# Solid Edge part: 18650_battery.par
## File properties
Last saved by: morva
Revision: 80
Density: 2861.43373586589 kg/m^3
Accuracy: 0.990
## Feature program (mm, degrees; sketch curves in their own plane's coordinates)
body "unnamed Body 1"
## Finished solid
Body 1: solid body, 41 faces, 104 edges, 60 vertices.
  Faces by surface: cylinder 17, torus 17, plane 7
  Edges by curve: circle 68, intersection 24, line 12
Bounding box of the edges (mm; curved faces can reach further): 18.000 x 18.000 x 65.000, from (-9, -9, 0) to (9, 9, 65).
Cylindrical faces by radius (mm): R1 x6, R3.95 x6, R4.25 x1, R6.5 x2, R9 x2
Toroidal faces (ring radius, tube radius in mm): R3.05 r1 x6, R3.2 r0.75 x6, R8 r1 x4, R9.65 r1 x1
Planar faces by outward normal: +z 4, -z 3
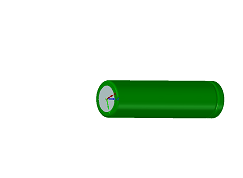
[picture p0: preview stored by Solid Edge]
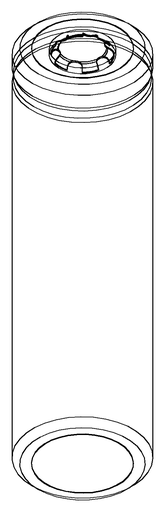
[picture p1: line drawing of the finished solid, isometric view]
